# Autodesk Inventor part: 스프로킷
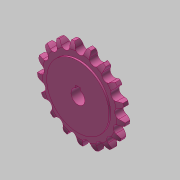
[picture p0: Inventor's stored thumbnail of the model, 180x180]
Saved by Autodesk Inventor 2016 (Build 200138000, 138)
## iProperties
Created: 2019-06
Part Number: 스프로킷
Material: 알루미늄 6061
Document SubType Name: Modeling
Designer: mduedu
Density: 1 g/cm^3
Appearance: 분홍색
Author: mduedu
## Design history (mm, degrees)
sketch "스케치1"
  geometry: L1 (0, 0)-(-3.6, 0); L2 (-3.6, 0)-(-3.6, 32.203); L3 (-2, 38)-(0, 38); L4 (0, 38)-(0, 0); L5 (0, 0)-(3.6, 0); L6 (3.6, 0)-(3.6, 32.203); L7 (2, 38)-(0, 38); A1 r 13.5 centre (9.887, 31.6) between (-2, 38) and (-3.6, 32.203); A2 r 13.5 centre (-9.887, 31.6) between (3.6, 32.203) and (2, 38)
  constraints: 14 end point, 4 point on circle, 4 symmetric about line, 2 centre point, 2 perpendicular, 1 horizontal, 1 parallel, 1 other
  dimensions: "d0" = 76 diameter of L3 L1; "d2" = 7.2 distance between parallel lines of L6 L2; "d3" = 1.6 distance from line of L3.start L2; "d4" = 6.4 distance from line of A2.centre L3; "d5" = 13.5 radius of A1
revolve "회전1" sketch "스케치1" stored, may be unused: angle "d6" = 90 deg
sketch "스케치2"
  geometry: L1 (34.56, 0)-(-34.56, 0); A1 r 34.56 centre (0, 0) between (34.56, 0) and (30.537, -16.182); A2 r 3.975 centre (34.56, 0) between (33.601, 3.858) and (33.601, -3.858); A3 r 12.7 centre (30.537, -16.182) between (37.583, -5.616) and (33.601, -3.858); A4 r 12.7 centre (30.537, 16.182) between (33.601, 3.858) and (37.583, 5.616); A5 r 38 centre (0, 0) between (37.583, -5.616) and (37.583, 5.616); 2 further points
  constraints: 11 point on circle, 5 centre point, 2 coincident, 2 end point, 2 symmetric about line, 1 horizontal, 1 horizontal alignment, 1 tangent, 3 other
  dimensions: "d7" = 69.12 diameter of A1; "d8" = 7.95 diameter of A2; "d9" = 12.7 radius of A3
extrude "돌출1" cut sketch "스케치2" stored distance "d10" = 10; taper "d11" = 0 deg
sketch "스케치3"
  geometry: C1 r 27 at (0, 0); 1 further point
  constraints: 1 centre point, 1 coincident
  dimensions: "d15" = 54 diameter of C1
extrude "돌출2" join sketch "스케치3" stored distance "d16" = 10; taper "d17" = 0 deg
sketch "스케치4"
  geometry: C1 r 11 at (0, 0); 1 further point
  constraints: 1 centre point, 1 coincident
  dimensions: "d18" = 22 diameter of C1
extrude "돌출3" join sketch "스케치4" distance "d19" = 11; taper "d20" = 0 deg
fillet "모깎기1" dims "d21" = 3
sketch "스케치5"
  geometry: L1 (-2, 5.657)-(2, 5.657); L2 (2, 5.657)-(2, 7.8); L3 (2, 7.8)-(-2, 7.8); L4 (-2, 7.8)-(-2, 5.657); A1 r 6 centre (0, 0) between (-2, 5.657) and (2, 5.657); 1 further point
  constraints: 8 end point, 2 parallel, 2 point on circle, 1 centre point, 1 coincident, 1 horizontal, 1 perpendicular
  dimensions: "d24" = 13.8 dimension on A1 L3; "d26" = 4 distance between parallel lines of L2 L4; "d27" = 12 diameter of A1
extrude "돌출4" cut sketch "스케치5" stored distance "d28" = 11; taper "d29" = 0 deg
chamfer "모따기1" distance "d30" = 0.5; stored, may be unused: second distance "d31" = 2, angle "d32" = 45 deg
node "솔리드1"
pattern_circular "원형 패턴1" dims angle "d13" = 360 deg
